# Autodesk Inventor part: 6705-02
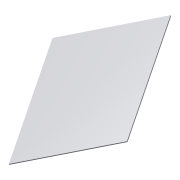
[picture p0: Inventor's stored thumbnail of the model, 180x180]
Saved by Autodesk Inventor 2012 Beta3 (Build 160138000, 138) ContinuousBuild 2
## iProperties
Created: 2011-02
Part Number: 6705-02
Material: Default
Document SubType Name: Modeling
Designer: Beta-8540w
Density: 1 g/cm^3
Author: Beta-8540w
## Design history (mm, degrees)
derived "c15-15.ipt" dims "d3" = 0, "drawer_depth" = 406.4, "bottom_width" = 450.85, "bottom_thickness" = 3.302
body "Solid1"
feature "Solid1::c15-15.ipt" dims "d3" = 0, "drawer_depth" = 406.4, "bottom_width" = 450.85, "bottom_thickness" = 3.302, "ScaleForDerivedMember" = 10
tag "TaggingFeature1"
